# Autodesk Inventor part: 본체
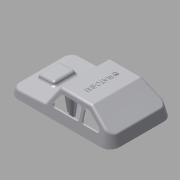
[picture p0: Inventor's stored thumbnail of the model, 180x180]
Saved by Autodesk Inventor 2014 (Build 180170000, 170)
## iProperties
Created: 2015-05
Part Number: 본체
Material: ABS 플라스틱
Document SubType Name: Modeling
Designer: Administrator
Density: 1.06 g/cm^3
Appearance: 매끄러움 - 흰색
Mass: 33.3276 g
Surface Area: 311.374 cm^2
Volume: 31.4411 cm^3
Author: Administrator
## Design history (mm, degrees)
sketch "스케치6"
  geometry: L1 (-49, -38)-(49, -38); L2 (61, -26)-(61, 26); L3 (49, 38)-(-49, 38); L4 (-61, 26)-(-61, -26); L5 (-61, -38)-(61, 38); L6 (61, -38)-(-61, 38); A1 r 12 centre (-49, 26) between (-49, 38) and (-61, 26); A2 r 12 centre (-49, -26) between (-61, -26) and (-49, -38); A3 r 12 centre (49, -26) between (49, -38) and (61, -26); A4 r 12 centre (49, 26) between (61, 26) and (49, 38); 1 further point
  constraints: 12 end point, 8 point on circle, 8 point on line, 8 tangent, 4 centre point, 3 equal radius, 2 midpoint, 2 parallel, 1 horizontal, 1 perpendicular
  dimensions: "d15" = 122 distance of L6.end L5.end; "d16" = 76 distance of L5.end L6.start; "d17" = 12 radius of A1
extrude "돌출4" new body sketch "스케치6" distance "d18" = 30; taper "d19" = -15 deg
sketch "스케치7"
  geometry: L1 (-31, 30)-(-61, 30); L2 (-61, 30)-(-61, 10); L3 (-61, 10)-(-31, 30); L4 (49, 30)-(-49, 30) reference; 3 further points
  constraints: 6 end point, 1 collinear, 1 horizontal, 1 midpoint, 1 perpendicular, 1 vertical alignment
  dimensions: "d20" = 20 vertical distance of L1.start L2.end; "d21" = 30 horizontal distance of L1.start L2.end
extrude "돌출5" cut sketch "스케치7" stored distance "d22" = 30; taper "d23" = 0 deg
sketch "스케치8"
  geometry: L1 (6.558, 30)-(19, 10.089); L2 (19, 10.089)-(58.856, 8); L3 (61, 0)-(52.962, 30) reference; L4 (49, 30)-(-31, 30) reference; L5 (-49, 0)-(49, 0) reference; L6 (61, 0)-(49, 0) reference; L7 (49, 30)-(52.962, 30) reference; 1 further point
  constraints: 4 end point, 2 point on line
  dimensions: "d24" = 8 vertical distance of L3.start L2.end; "d25" = 42 horizontal distance of L3.start L1.end; "d26" = 125 deg angle of L2 L1; "d27" = 3 deg angle of L5 L2
extrude "돌출6" cut sketch "스케치8" stored distance "d28" = 30; taper "d29" = 0 deg
sketch "스케치9"
  geometry: L1 (-39.911, 9.297)-(-39.911, 61.297) reference; L2 (-31.47, 48.297)-(-11.47, 48.297); L3 (-11.47, 48.297)-(-11.47, 22.297); L4 (-11.47, 22.297)-(-31.47, 22.297); L5 (-31.47, 22.297)-(-31.47, 48.297); L6 (-42.47, 61.297)-(-42.47, 9.297) reference; 3 further points
  constraints: 8 end point, 2 midpoint, 2 parallel, 1 horizontal, 1 horizontal alignment, 1 perpendicular
  dimensions: "d30" = 11 distance between parallel lines of L6 L5; "d31" = 20 distance of L2.start L2.end; "d32" = 26 distance of L2.end L3.end
extrude "돌출7" join sketch "스케치9" distance "d33" = 5; taper "d34" = 0 deg
fillet "모깎기1" dims "d35" = 3
fillet "모깎기2" dims "d36" = 3
fillet "모깎기3" dims "d37" = 3
fillet "모깎기4" dims "d38" = 3
feature "쉘1" dims "d39" = 2
node "작업 평면1"
sketch "스케치10"
  geometry: A1 r 4 centre (21, 0) between (25, 0) and (17, 0); A2 r 4 centre (10, 0) between (14, 0) and (6, 0); A3 r 4 centre (-10, 0) between (-6, 0) and (-14, 0); A4 r 4 centre (-21, 0) between (-17, 0) and (-25, 0); 3 further points
  constraints: 8 point on circle, 4 centre point, 13 other
  dimensions: "d41" = 8 diameter of A1; "d42" = 8 diameter of A2; "d43" = 8 diameter of A3; "d44" = 8 diameter of A4; "d45" = 10 distance of A3.centre point (0, 0); "d46" = 20 distance of A2.centre A3.centre; "d47" = 11 distance of A1.centre A2.centre; "d48" = 11 distance of A3.centre A4.centre
extrude "돌출8" join sketch "스케치10" stored distance "d49" = 5; taper "d50" = 0 deg
chamfer "모따기1" distance "d51" = 1; stored, may be unused: second distance "d52" = 2, angle "d53" = 45 deg
sketch "스케치11"
  geometry: L1 (4.895, 30)-(-30.092, 30) reference; L2 (18.172, 11.413)-(7.439, 28.59) reference; L3 (-31.756, 29.496)-(-50.664, 16.891) reference; L4 (2.124, 25)-(-17.84, 25); L5 (10.292, 14.59)-(4.668, 23.59); L6 (7.747, 10)-(-17.84, 10); L7 (-20.84, 13)-(-20.84, 22); L8 (-30.242, 24.496)-(-43.742, 15.496); L9 (-42.078, 10)-(-26.986, 10); L10 (-23.986, 13)-(-23.986, 22); L11 (-26.986, 25)-(-28.578, 25); A1 r 3 centre (7.747, 13) between (7.747, 10) and (10.292, 14.59); A2 r 3 centre (2.124, 22) between (4.668, 23.59) and (2.124, 25); A3 r 3 centre (-17.84, 22) between (-17.84, 25) and (-20.84, 22); A4 r 3 centre (-17.84, 13) between (-20.84, 13) and (-17.84, 10); A5 r 3 centre (-26.986, 22) between (-23.986, 22) and (-26.986, 25); A6 r 3 centre (-28.578, 22) between (-28.578, 25) and (-30.242, 24.496); A7 r 3 centre (-42.078, 13) between (-43.742, 15.496) and (-42.078, 10); A8 r 3 centre (-26.986, 13) between (-26.986, 10) and (-23.986, 13); 7 further points
  constraints: 16 end point, 16 point on circle, 16 tangent, 12 point on line, 8 centre point, 6 equal radius, 5 parallel, 3 perpendicular
  dimensions: "d54" = 5 distance between parallel lines of L2 L5; "d55" = 5 distance between parallel lines of L1 L4; "d56" = 34 distance of point (13.16, 10) point (-20.84, 10); "d57" = 15 distance of point (-20.84, 10) point (-20.84, 25); "d58" = 3 radius of A1; "d59" = 5 distance between parallel lines of L3 L8; "d60" = 5 distance between parallel lines of L1 L11; "d61" = 15 distance of point (-23.986, 10) point (-23.986, 25); "d62" = 28 distance of point (-51.986, 10) point (-23.986, 10); "d63" = 3 radius of A5
extrude "돌출9" cut sketch "스케치11" stored distance "d64" = 5; taper "d65" = 0 deg
sketch "스케치12"
  geometry: L1 (58.929, 26)-(58.929, -26) reference; L2 (49, -35.929)-(-49, -35.929) reference; L3 (-58.929, -26)-(-58.929, 26) reference; L4 (-49, 35.929)-(49, 35.929) reference; L5 (49, 36.929)-(-49, 36.929); L6 (-59.929, 26)-(-59.929, -26); L7 (-49, -36.929)-(49, -36.929); L8 (59.929, -26)-(59.929, 26); A1 r 9.929 centre (49, -26) between (49, -35.929) and (58.929, -26) reference; A2 r 9.929 centre (-49, -26) between (-58.929, -26) and (-49, -35.929) reference; A3 r 9.929 centre (-49, 26) between (-49, 35.929) and (-58.929, 26) reference; A4 r 9.929 centre (49, 26) between (58.929, 26) and (49, 35.929) reference; A5 r 10.929 centre (-49, 26) between (-49, 36.929) and (-59.929, 26); A6 r 10.929 centre (-49, -26) between (-59.929, -26) and (-49, -36.929); A7 r 10.929 centre (49, -26) between (49, -36.929) and (59.929, -26); A8 r 10.929 centre (49, 26) between (59.929, 26) and (49, 36.929); 1 further point
  constraints: 8 end point, 8 point on circle, 4 centre point, 7 other
  dimensions: "d66" = 1 distance between parallel lines of L5 L4
extrude "돌출10" join sketch "스케치12" distance "d67" = 1; taper "d68" = 0 deg
sketch "스케치13"
  geometry: C1 r 3 at (40, 0); C2 r 3 at (0, -22); C3 r 3 at (0, 22); C4 r 3 at (-40, 0); 1 further point
  constraints: 4 centre point, 2 horizontal alignment, 2 vertical alignment
  dimensions: "d69" = 6 diameter of C1; "d70" = 6 diameter of C2; "d71" = 6 diameter of C3; "d72" = 6 diameter of C4; "d73" = 22 distance of C2.centre point (0, 0); "d74" = 44 distance of C2.centre C3.centre; "d75" = 40 distance of point (0, 0) C1.centre; "d76" = 40 distance of point (0, 0) C4.centre
extrude "돌출11" join sketch "스케치13" stored distance "d77" = 1; taper "d78" = 4 deg
node "작업 평면2"
sketch "스케치18"
  geometry: L1 (-45, 1)-(-35, 1); L2 (-35, 1)-(-35, -1); L3 (-35, -1)-(-45, -1); L4 (-45, -1)-(-45, 1); L5 (-45, 1)-(-35, -1); L6 (-35, 1)-(-45, -1); L7 (-5, 23)-(5, 23); L8 (5, 23)-(5, 21); L9 (5, 21)-(-5, 21); L10 (-5, 21)-(-5, 23); L11 (-5, 23)-(5, 21); L12 (5, 23)-(-5, 21); L13 (-5, -21)-(5, -21); L14 (5, -21)-(5, -23); L15 (5, -23)-(-5, -23); L16 (-5, -23)-(-5, -21); L17 (-5, -21)-(5, -23); L18 (5, -21)-(-5, -23); L19 (35, 1)-(45, 1); L20 (45, 1)-(45, -1); L21 (45, -1)-(35, -1); L22 (35, -1)-(35, 1); L23 (35, 1)-(45, -1); L24 (45, 1)-(35, -1); C1 r 3 at (0, 22) reference; C2 r 3 at (-40, 0) reference; C3 r 3 at (0, -22) reference; C4 r 3 at (40, 0) reference; 1 further point
  constraints: 48 end point, 8 midpoint, 8 parallel, 4 horizontal, 4 perpendicular
  dimensions: "d101" = 10 distance of L2.end L3.end; "d102" = 2 distance of L1.end L2.end; "d103" = 10 distance of L8.end L9.end; "d104" = 2 distance of L7.end L8.end; "d105" = 10 distance of L14.end L15.end; "d106" = 2 distance of L13.end L14.end; "d107" = 10 distance of L20.end L21.end; "d108" = 2 distance of L19.end L20.end
extrude "돌출15" join sketch "스케치18" stored distance "d109" = 2; taper "d110" = 2.5 deg
sketch "스케치19"
  geometry: L1 (1.498, 26.025)-(3.159, 26.025) reference; L2 (2.024, 0)-(0, 0) reference; L3 (2.024, 0)-(3.159, 26.025) reference; L4 (2.024, 0)-(6.613, 26.025); L5 (6.613, 26.025)-(1.498, 26.025); 1 further point
  constraints: 4 end point, 1 collinear, 1 other
  dimensions: "d111" = 80 deg angle of L5 L4
extrude "돌출16" join sketch "스케치19" stored distance "d112" = 2; taper "d113" = 0 deg
sketch "스케치20"
  geometry: L1 (-1.09, 24.998)-(-0.743, 25.554) reference; L2 (0, 0)-(-1.09, 24.998) reference; L3 (0, 0)-(-3.677, 20.854); L4 (-1.09, 24.998)-(-3.677, 20.854); L5 (35.092, 24.902)-(0.105, 24.902) reference; 1 further point
  constraints: 4 end point, 1 collinear
  dimensions: "d114" = 80 deg angle of L5 L3
extrude "돌출17" join sketch "스케치20" stored distance "d115" = 2; taper "d116" = 0 deg
sketch "스케치21"
  geometry: L1 (0.984, 16.972)-(2.714, 15.818) reference; L2 (2.024, 0)-(2.714, 15.818) reference; L3 (2.024, 0)-(4.592, 14.565); L4 (2.714, 15.818)-(4.592, 14.565); L5 (-12.885, 23.943)-(-47.872, 23.943) reference; 1 further point
  constraints: 4 end point, 1 collinear
  dimensions: "d117" = 80 deg angle of L5 L3
extrude "돌출18" join sketch "스케치21" stored distance "d118" = 2; taper "d119" = 0 deg
sketch "스케치22"
  geometry: L1 (-1.031, 23.64)-(0.727, 22.466) reference; L2 (0, 0)-(-1.031, 23.64) reference; L3 (0, 0)-(-4.587, 26.012); L4 (-1.031, 23.64)-(-4.587, 26.012); L5 (-39.895, 26.723)-(-4.908, 26.723) reference; 1 further point
  constraints: 4 end point, 1 collinear
  dimensions: "d120" = 80 deg angle of L5 L3
extrude "돌출19" join sketch "스케치22" stored distance "d121" = 2; taper "d122" = 0 deg
sketch "스케치23"
  geometry: L1 (2.472, -10.288)-(0.594, -10.189) reference; L2 (2.024, 0)-(2.472, -10.288) reference; L3 (0, 0)-(2.024, 0) reference; L4 (2.024, 0)-(3.286, -10.288); L5 (2.472, -10.288)-(3.286, -10.288); 1 further point
  constraints: 4 end point, 1 parallel
  dimensions: "d123" = 80 deg angle of L1 L4
extrude "돌출20" join sketch "스케치23" stored distance "d124" = 2; taper "d125" = 0 deg
sketch "스케치24"
  geometry: L1 (0, 0)-(-0.424, -9.717) reference; L2 (0, 0)-(-2.137, -9.643); L3 (-0.424, -9.717)-(-2.137, -9.643); 1 further point
  constraints: 4 end point, 1 perpendicular
  dimensions: "d126" = 80 deg angle of L3 L2
extrude "돌출21" join sketch "스케치24" stored distance "d127" = 2; taper "d128" = 0 deg
hole "구멍1" diameter "d131" = 3.242; stored, may be unused: countersink angle "d135" = 90 deg, drill point angle "d137" = 118 deg; dims "d129" = 10, "d130" = 10, "d132" = 9, "d133" = 4, "d134" = 2, "d136" = 11
hole "구멍2" diameter "d140" = 3.242; stored, may be unused: countersink angle "d144" = 90 deg, drill point angle "d146" = 118 deg; dims "d138" = 10, "d139" = 10, "d141" = 9, "d142" = 4, "d143" = 2, "d145" = 11
hole "구멍3" diameter "d149" = 3.242; stored, may be unused: countersink angle "d153" = 90 deg, drill point angle "d155" = 118 deg; dims "d147" = 10, "d148" = 10, "d150" = 9, "d151" = 4, "d152" = 2, "d154" = 11
hole "구멍4" diameter "d158" = 3.242; stored, may be unused: countersink angle "d162" = 90 deg, drill point angle "d164" = 118 deg; dims "d156" = 10, "d157" = 10, "d159" = 9, "d160" = 4, "d161" = 2, "d163" = 11
sketch "스케치26"
  geometry: 2 further points
  constraints: 1 other
feature "엠보싱2" sketch "스케치26" dims "d15" = 122, "d16" = 76, "d17" = 12, "d167" = 0.5, "d168" = 0
node "솔리드3"
mirror "대칭2"
node "투영된 루프4"
node "투영된 루프5"
node "투영된 루프6"
node "투영된 루프7"
other parameters: "d40" = -63, "d79" = 2
